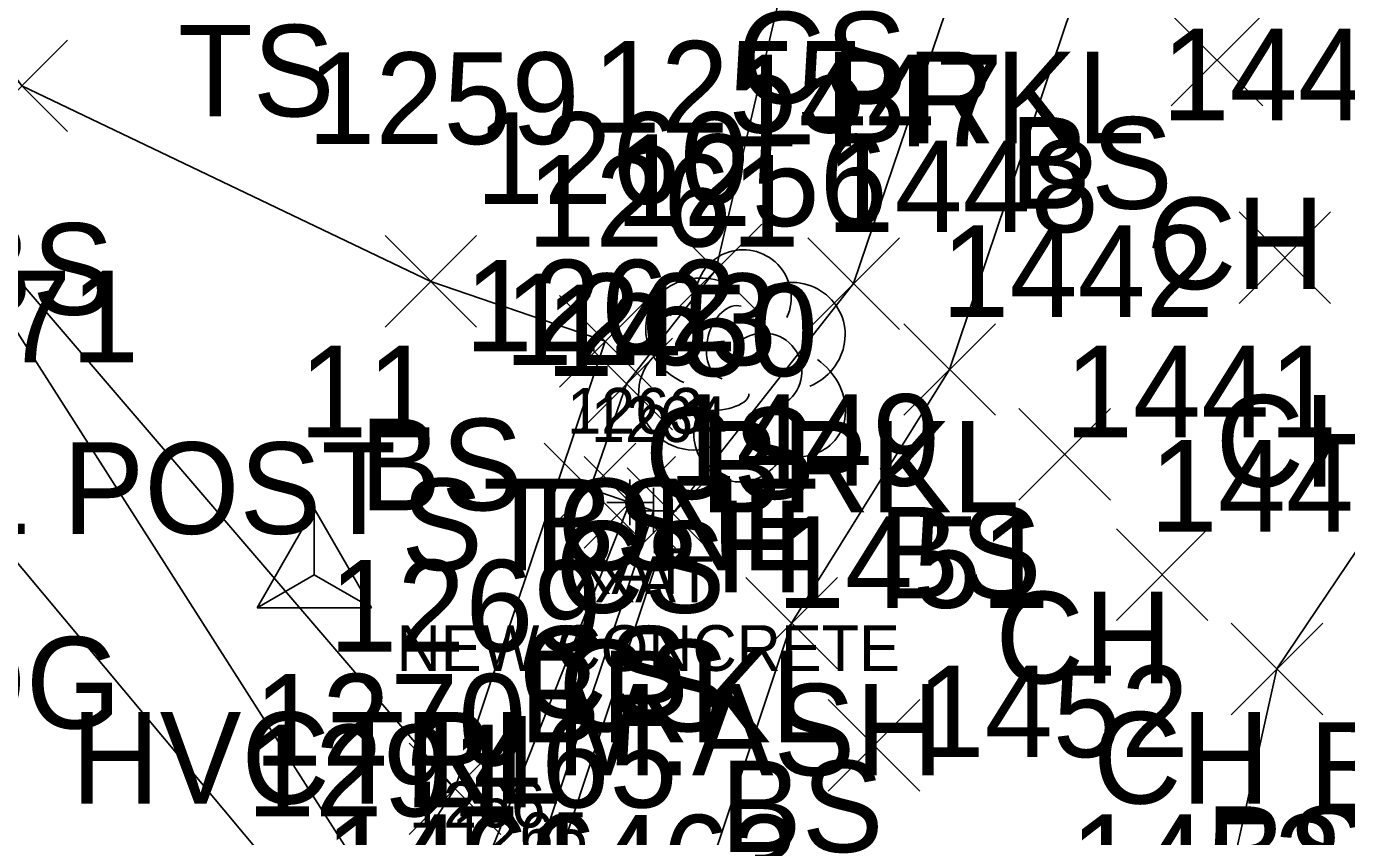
# Model space of a CAD drawing. Extents: x 1441651 to 1442140, y 243798 to 245625.
# Drawn here: x 1442046.7 to 1442075.54, y 245426.94 to 245444.63 of the extents above; entities that cross this region are included whole.
import ezdxf

# ---------------------------------------------------------------- set-up
doc = ezdxf.new("R2010")
doc.units = 0
for name, color, linetype in [('B_A', 7, 'Continuous'), ('B_C', 7, 'Continuous'), ('B_I', 7, 'Continuous'), ('B_TIC', 7, 'Continuous'), ('BSUBM', 7, 'Continuous'), ('C_A', 7, 'Continuous'), ('C_I', 7, 'Continuous'), ('CPSM', 7, 'Continuous'), ('L_A', 7, 'Continuous'), ('L_C', 7, 'Continuous'), ('L_I', 7, 'Continuous'), ('L_TIC', 7, 'Continuous'), ('LASF', 7, 'Continuous'), ('LAWE', 7, 'Continuous'), ('LELB', 7, 'Continuous'), ('LTD', 7, 'Continuous'), ('P_A', 7, 'Continuous'), ('P_I', 7, 'Continuous'), ('PEU', 7, 'Continuous'), ('R_C', 7, 'Continuous'), ('R_I', 7, 'Continuous'), ('RGR', 7, 'Continuous')]:
    doc.layers.add(name, color=color, linetype=linetype)

msp = doc.modelspace()

# ---------------------------------------------------------------- linework, layer by layer
at = {"layer": 'B_TIC'}
for p, q in [((1442059.886, 245434.236), (1442059.961, 245434.236)), ((1442059.886, 245434.236), (1442059.961, 245434.236)), ((1442060.404, 245434.055), (1442060.48, 245434.055))]:
    msp.add_line(p, q, dxfattribs=at)
for points in [[(1442059.882, 245433.736), (1442059.882, 245434.736)], [(1442059.882, 245433.736), (1442059.882, 245434.736)], [(1442060.401, 245433.555), (1442060.401, 245434.555)], [(1442059.382, 245434.236), (1442060.382, 245434.236)], [(1442059.382, 245434.236), (1442060.382, 245434.236)], [(1442059.901, 245434.055), (1442060.901, 245434.055)]]:
    msp.add_lwpolyline(points, dxfattribs=at)
at = {"layer": 'BSUBM'}
for points in [[(1442059.882, 245434.236), (1442060.401, 245434.055), (1442057.354, 245424.964), (1442050.715, 245417.356), (1442043.353, 245410.307), (1442039.483, 245407.236)], [(1442059.882, 245434.236), (1442056.459, 245425.635), (1442055.228, 245424.098), (1442049.56, 245418.588)]]:
    msp.add_lwpolyline(points, dxfattribs=at)
at = {"layer": 'CPSM'}
for p, q in [((1442051.738, 245431.937), (1442052.988, 245434.102)), ((1442054.238, 245431.937), (1442052.988, 245434.102)), ((1442052.989, 245432.658), (1442052.988, 245434.102)), ((1442051.738, 245431.937), (1442052.989, 245432.658)), ((1442052.989, 245432.658), (1442052.989, 245432.658)), ((1442052.989, 245432.658), (1442054.238, 245431.937)), ((1442051.738, 245431.937), (1442054.238, 245431.937))]:
    msp.add_line(p, q, dxfattribs=at)
at = {"layer": 'L_TIC'}
for points in [[(1442071.709, 245442.895), (1442073.709, 245444.895)], [(1442073.709, 245442.895), (1442071.709, 245444.895)], [(1442045.602, 245442.334), (1442047.602, 245444.334)], [(1442047.602, 245442.334), (1442045.602, 245444.334)], [(1442073.188, 245438.58), (1442075.188, 245440.58)], [(1442075.188, 245438.58), (1442073.188, 245440.58)], [(1442060.763, 245438.313), (1442062.763, 245440.313)], [(1442062.763, 245438.313), (1442060.763, 245440.313)], [(1442054.536, 245438.064), (1442056.536, 245440.064)], [(1442056.536, 245438.064), (1442054.536, 245440.064)], [(1442063.769, 245438.016), (1442065.769, 245440.016)], [(1442065.769, 245438.016), (1442063.769, 245440.016)], [(1442058.345, 245436.756), (1442060.345, 245438.756)], [(1442060.345, 245436.756), (1442058.345, 245438.756)], [(1442058.345, 245436.756), (1442060.345, 245438.756)], [(1442060.345, 245436.756), (1442058.345, 245438.756)], [(1442065.867, 245436.139), (1442067.867, 245438.139)], [(1442067.867, 245436.139), (1442065.867, 245438.139)], [(1442058.812, 245435.825), (1442060.812, 245437.825)], [(1442060.812, 245435.825), (1442058.812, 245437.825)], [(1442068.378, 245434.285), (1442070.378, 245436.285)], [(1442070.378, 245434.285), (1442068.378, 245436.285)], [(1442058.013, 245433.533), (1442060.013, 245435.533)], [(1442060.013, 245433.533), (1442058.013, 245435.533)], [(1442058.882, 245433.236), (1442060.882, 245435.236)], [(1442060.882, 245433.236), (1442058.882, 245435.236)], [(1442059.82, 245432.995), (1442061.82, 245434.995)], [(1442061.82, 245432.995), (1442059.82, 245434.995)], [(1442070.509, 245431.659), (1442072.509, 245433.659)], [(1442072.509, 245431.659), (1442070.509, 245433.659)], [(1442062.415, 245430.599), (1442064.415, 245432.599)], [(1442064.415, 245430.599), (1442062.415, 245432.599)], [(1442073.016, 245429.6), (1442075.016, 245431.6)], [(1442075.016, 245429.6), (1442073.016, 245431.6)], [(1442064.217, 245427.933), (1442066.217, 245429.933)], [(1442066.217, 245427.933), (1442064.217, 245429.933)], [(1442055.061, 245426.98), (1442057.061, 245428.98)], [(1442057.061, 245426.98), (1442055.061, 245428.98)], [(1442055.061, 245426.98), (1442057.061, 245428.98)], [(1442057.061, 245426.98), (1442055.061, 245428.98)]]:
    msp.add_lwpolyline(points, dxfattribs=at)
at = {"layer": 'LASF'}
msp.add_lwpolyline([(1442059.345, 245437.756), (1442056.061, 245427.98), (1442054.448, 245425.49)], dxfattribs=at)
at = {"layer": 'LAWE'}
msp.add_lwpolyline([(1442099.331, 245492.7), (1442082.175, 245474.825), (1442073.962, 245459.556), (1442071.044, 245454.669), (1442067.5, 245447.08), (1442064.769, 245439.016), (1442060.82, 245433.995), (1442057.711, 245424.573), (1442056.016, 245422.421), (1442050.947, 245416.77), (1442046.422, 245406.149), (1442038.474, 245397.39), (1442032.995, 245390.022), (1442022.028, 245379.959), (1442015.438, 245373.014), (1442011.82, 245364.946), (1441999.311, 245341.928), (1441993.277, 245326.588), (1441983.696, 245301.797)], dxfattribs=at)
at = {"layer": 'LELB'}
for points in [[(1441958.143, 245603.853), (1441973.054, 245572.702), (1441987.155, 245544.678), (1442001.278, 245515.813), (1442017.222, 245492.134), (1442028.726, 245467.165), (1442040.19, 245452.018), (1442046.602, 245443.334), (1442055.536, 245439.064), (1442059.345, 245437.756)], [(1441951.999, 245600.361), (1441967.384, 245569.64), (1441982.753, 245541.997), (1441998.178, 245514.398), (1442013.668, 245490.085), (1442025.646, 245464.596), (1442043.563, 245442.549), (1442056.061, 245427.98)], [(1442102.458, 245487.565), (1442084.345, 245473.245), (1442077.162, 245458.74), (1442072.716, 245452.8), (1442069.733, 245445.651), (1442066.867, 245437.139), (1442063.415, 245431.599), (1442060.353, 245422.411), (1442058.711, 245418.726), (1442054.414, 245414.049), (1442047.261, 245402.979), (1442041.756, 245394.877), (1442035.105, 245387.217), (1442025.138, 245377.826), (1442014.243, 245362.921), (1442001.678, 245340.269), (1441995.167, 245325.255), (1441985.519, 245301.167)], [(1442107.479, 245478.045), (1442095.111, 245463.136), (1442085.124, 245450.231), (1442079.931, 245439.38), (1442074.016, 245430.6), (1442072.192, 245422.421), (1442067.602, 245415.77), (1442063.525, 245410.875), (1442058.938, 245403.451), (1442051.468, 245396.66), (1442047.361, 245390.552), (1442031.625, 245371.637), (1442024.894, 245355.937), (1442013.328, 245334.791), (1442005.478, 245318.663), (1441997.832, 245296.612)], [(1442068.683, 245457.119), (1442063.778, 245447.95), (1442061.763, 245439.313), (1442059.812, 245436.825), (1442059.013, 245434.533), (1442059.882, 245434.236)]]:
    msp.add_lwpolyline(points, dxfattribs=at)
at = {"layer": 'LTD'}
msp.add_line((1442062.313, 245437.273), (1442062.313, 245437.273), dxfattribs=at)
msp.add_line((1442062.313, 245437.273), (1442062.313, 245437.273), dxfattribs=at)
msp.add_arc((1442062.36, 245438.707), 1.047, 335.5272, 180.9563, dxfattribs=at)
for centre, major_axis, ratio, start_param, end_param in [((1442061.522, 245437.939), (1.21, -0.512), 0.895232, 1.570796, 4.712389), ((1442063.355, 245437.856), (-1.141, -0.483), 0.949671, 1.570796, 4.712389), ((1442062.105, 245437.731), (-0.208, -0.792), 0.645439, 3.141593, 6.283185), ((1442062.813, 245437.106), (-0.5, 0.667), 0.989748, 3.141593, 6.283185), ((1442061.23, 245436.564), (0.584, -1.042), 0.959034, 3.141593, 6.283185), ((1442063.314, 245436.44), (-1.09, 0.792), 0.841452, 1.570796, 4.712389), ((1442061.855, 245436.523), (-0.625, -0.083), 0.423636, 0, 3.141593), ((1442062.314, 245435.773), (0.265, 1.061), 0.942809, 1.570796, 4.712389)]:
    msp.add_ellipse(centre, major_axis=major_axis, ratio=ratio, start_param=start_param, end_param=end_param, dxfattribs=at)
at = {"layer": 'PEU'}
msp.add_lwpolyline([(1441949.699, 245598.806), (1441965.584, 245568.638), (1441979.812, 245540.541), (1441994.499, 245512.774), (1442011.015, 245488.252), (1442024.854, 245464.866), (1442045.339, 245434.299), (1442053.641, 245424.38)], dxfattribs=at)
at = {"layer": 'RGR'}
msp.add_lwpolyline([(1442043.563, 245442.549), (1442054.448, 245425.49)], dxfattribs=at)

# ---------------------------------------------------------------- texts
at = {"layer": 'B_A'}
for p in [(1442058.587, 245432.236), (1442058.587, 245432.236), (1442059.105, 245432.055)]:
    msp.add_text('XAT', height=1, dxfattribs=at).set_placement(p)
at = {"layer": 'B_C'}
msp.add_text('NEW CONCRETE', height=1, dxfattribs=at).set_placement((1442054.787, 245430.555))
at = {"layer": 'B_I'}
for s, p in [('1263', (1442058.512, 245435.736)), ('1263', (1442058.512, 245435.736)), ('1264', (1442059.031, 245435.555)), ('1266', (1442055.061, 245427.135)), ('1265', (1442055.983, 245426.464))]:
    msp.add_text(s, height=1, dxfattribs=at).set_placement(p)
at = {"layer": 'C_A'}
msp.add_text('HVCTRL', height=2, dxfattribs=at).set_placement((1442047.682, 245427.658))
at = {"layer": 'C_I'}
msp.add_text('11', height=2, dxfattribs=at).set_placement((1442052.658, 245435.658))
at = {"layer": 'L_A'}
for s, p in [('CS', (1442062.219, 245442.95)), ('TS', (1442050.014, 245442.667)), ('BRKL', (1442064.146, 245442.08)), ('BS', (1442068.174, 245440.651)), ('CH', (1442071.197, 245438.895)), ('BS', (1442045.043, 245438.334)), ('CH', (1442072.676, 245434.58)), ('CS', (1442060.204, 245434.313)), ('BS', (1442053.977, 245434.064)), ('BRKL', (1442061.415, 245434.016)), ('STONE', (1442054.888, 245432.756)), ('BS', (1442057.786, 245432.756)), ('H', (1442061.747, 245432.273)), ('BS', (1442065.308, 245432.139)), ('CS', (1442058.253, 245431.825)), ('CH', (1442067.867, 245430.285)), ('CS', (1442057.454, 245429.533)), ('CS', (1442058.323, 245429.236)), ('BRKL', (1442057.466, 245428.995)), ('CH', (1442069.998, 245427.659)), ('BRKR', (1442074.717, 245427.436)), ('BS', (1442061.855, 245426.599)), ('BS', (1442072.457, 245425.6))]:
    msp.add_text(s, height=2, dxfattribs=at).set_placement(p)
at = {"layer": 'L_C'}
msp.add_text('M.ASH', height=2, dxfattribs=at).set_placement((1442058.266, 245428.273))
at = {"layer": 'L_I'}
for s, p in [('1443', (1442071.495, 245442.58)), ('1255', (1442059.07, 245442.313)), ('1259', (1442052.836, 245442.064)), ('1447', (1442062.076, 245442.016)), ('1260', (1442056.518, 245440.756)), ('1260', (1442056.518, 245440.756)), ('1256', (1442059.565, 245440.273)), ('1448', (1442064.174, 245440.139)), ('1261', (1442057.639, 245439.825)), ('1442', (1442066.685, 245438.285)), ('1262', (1442056.273, 245437.533)), ('1263', (1442057.142, 245437.236)), ('1450', (1442058.04, 245436.995)), ('1441', (1442069.383, 245435.659)), ('1449', (1442060.714, 245434.599)), ('1440', (1442071.236, 245433.6)), ('1451', (1442063.091, 245431.933)), ('1269', (1442053.313, 245430.98)), ('1269', (1442053.313, 245430.98)), ('1270', (1442051.669, 245428.49)), ('1452', (1442066.145, 245428.673)), ('1465', (1442054.971, 245427.573)), ('1466', (1442053.221, 245425.421)), ('1463', (1442057.613, 245425.411)), ('1453', (1442069.5, 245425.421))]:
    msp.add_text(s, height=2, dxfattribs=at).set_placement(p)
at = {"layer": 'P_A'}
msp.add_text('RDG', height=2, dxfattribs=at).set_placement((1442042.827, 245429.299))
at = {"layer": 'P_I'}
for s, p in [('1271', (1442043.213, 245437.299)), ('1291', (1442051.515, 245427.38)), ('1291', (1442051.515, 245427.38))]:
    msp.add_text(s, height=2, dxfattribs=at).set_placement(p)
at = {"layer": 'R_C'}
msp.add_text('SGR W/ STEEL POST', height=2, dxfattribs=at).set_placement((1442027.728, 245433.549))
at = {"layer": 'R_I'}
msp.add_text('1270', height=2, dxfattribs=at).set_placement((1442051.669, 245428.49))

doc.saveas('drawing.dxf')
